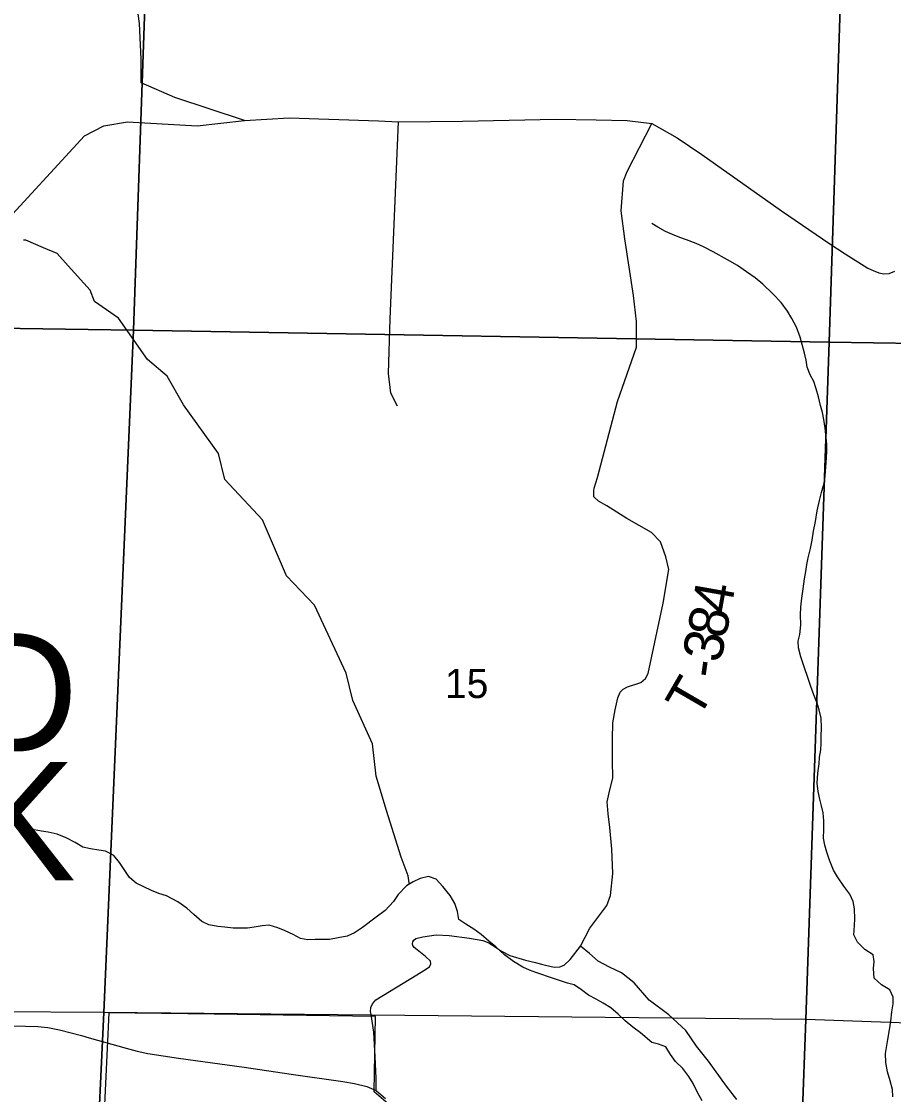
# Model space of a CAD drawing. Extents: x 0 to 34, y 0 to 22.
# Drawn here: x 3.296 to 4.552, y 15.005 to 16.55 of the extents above; entities that cross this region are included whole.
import ezdxf

# ---------------------------------------------------------------- set-up
doc = ezdxf.new("R2010")
doc.units = 0
for name, color, linetype in [('Default', 7, 'Continuous'), ('GM_X_County_Road', 7, 'Continuous'), ('GM_X_Minor_River', 7, 'Continuous'), ('GM_X_Section', 7, 'Continuous'), ('GM_X_Section_Text', 7, 'Continuous'), ('GM_X_Township_Road', 7, 'Continuous'), ('GM_X_Township_Road_Text', 7, 'Continuous'), ('GM_X_Township_Text', 7, 'Continuous')]:
    doc.layers.add(name, color=color, linetype=linetype)

msp = doc.modelspace()

# ---------------------------------------------------------------- linework, layer by layer
at = {"layer": 'Default'}
for p, q in [((3.4148, 15.1232), (2.428, 15.1288)), ((3.3681, 14.1), (3.4148, 15.1232)), ((3.4148, 15.1232), (3.3681, 14.1)), ((3.4223, 15.1228), (3.389, 14.4392)), ((4.4256, 15.1132), (3.4148, 15.1232)), ((3.5737, 15.1206), (3.4223, 15.1228)), ((3.8059, 15.1172), (3.5737, 15.1206)), ((3.8044, 15.0089), (3.8059, 15.1172)), ((4.3897, 14.1), (4.4256, 15.1132)), ((4.4256, 15.1132), (4.3897, 14.1)), ((5.4229, 15.0756), (4.4256, 15.1132)), ((3.8279, 14.9887), (3.8044, 15.0089))]:
    msp.add_line(p, q, dxfattribs=at)
at = {"layer": 'GM_X_County_Road'}
for p, q in [((3.4149, 16.3993), (3.4489, 16.405)), ((3.4489, 16.405), (3.457, 16.4045)), ((3.457, 16.4045), (3.5495, 16.3993)), ((3.5495, 16.3993), (3.6176, 16.4072)), ((3.6176, 16.4072), (3.682, 16.4109)), ((3.682, 16.4109), (3.8102, 16.4064)), ((3.8102, 16.4064), (3.8391, 16.4054)), ((3.8391, 16.4054), (3.9312, 16.4062)), ((3.9312, 16.4062), (4.0658, 16.4089)), ((4.0658, 16.4089), (4.1237, 16.4082)), ((4.1237, 16.4082), (4.1687, 16.4072)), ((4.1687, 16.4072), (4.204, 16.4026)), ((3.387, 16.3849), (3.4149, 16.3993)), ((4.204, 16.4026), (4.2406, 16.3821)), ((3.1953, 16.1767), (3.387, 16.3849)), ((4.2406, 16.3821), (4.276, 16.358)), ((4.276, 16.358), (4.3909, 16.2772)), ((4.3909, 16.2772), (4.4602, 16.2296)), ((4.4602, 16.2296), (4.4825, 16.215)), ((4.4825, 16.215), (4.5149, 16.1947)), ((4.5149, 16.1947), (4.5227, 16.1911)), ((4.5227, 16.1911), (4.5309, 16.1878)), ((4.5459, 16.1869), (4.5541, 16.19)), ((4.5309, 16.1878), (4.5379, 16.1864)), ((4.5379, 16.1864), (4.5459, 16.1869)), ((3.2648, 15.104), (3.302, 15.1035)), ((3.302, 15.1035), (3.3198, 15.1028)), ((3.3198, 15.1028), (3.3345, 15.1014)), ((3.3345, 15.1014), (3.3509, 15.0983)), ((3.3509, 15.0983), (3.383, 15.0898)), ((3.383, 15.0898), (3.3936, 15.0868)), ((3.3936, 15.0868), (3.4469, 15.0716)), ((3.4469, 15.0716), (3.4631, 15.0672)), ((3.4631, 15.0672), (3.4785, 15.0639)), ((3.4785, 15.0639), (3.5226, 15.0573)), ((3.5226, 15.0573), (3.6172, 15.0446)), ((3.6172, 15.0446), (3.6849, 15.0343)), ((3.6849, 15.0343), (3.759, 15.0237)), ((3.759, 15.0237), (3.776, 15.0208)), ((3.776, 15.0208), (3.7937, 15.0168)), ((3.7937, 15.0168), (3.8069, 15.0107)), ((3.8069, 15.0107), (3.8205, 14.9991))]:
    msp.add_line(p, q, dxfattribs=at)
at = {"layer": 'GM_X_Minor_River'}
for p, q in [((4.2127, 16.2536), (4.2038, 16.259)), ((4.2236, 16.2471), (4.2127, 16.2536)), ((3.3027, 16.235), (3.2993, 16.2349)), ((3.3282, 16.224), (3.3027, 16.235)), ((4.2336, 16.2428), (4.2236, 16.2471)), ((4.2444, 16.2386), (4.2336, 16.2428)), ((4.254, 16.2355), (4.2444, 16.2386)), ((4.2678, 16.2302), (4.254, 16.2355)), ((3.348, 16.2155), (3.3282, 16.224)), ((4.2786, 16.2252), (4.2678, 16.2302)), ((4.2921, 16.218), (4.2786, 16.2252)), ((3.3638, 16.1979), (3.348, 16.2155)), ((4.313, 16.2065), (4.2921, 16.218)), ((4.3273, 16.1982), (4.313, 16.2065)), ((3.3954, 16.1631), (3.3638, 16.1979)), ((4.3405, 16.1894), (4.3273, 16.1982)), ((4.3526, 16.1807), (4.3405, 16.1894)), ((4.3639, 16.1715), (4.3526, 16.1807)), ((3.4014, 16.1464), (3.3954, 16.1631)), ((4.378, 16.1575), (4.3639, 16.1715)), ((4.3902, 16.1449), (4.378, 16.1575)), ((3.4362, 16.1227), (3.4014, 16.1464)), ((4.3993, 16.1327), (4.3902, 16.1449)), ((4.4057, 16.1222), (4.3993, 16.1327)), ((3.4777, 16.0629), (3.4362, 16.1227)), ((4.4122, 16.1095), (4.4057, 16.1222)), ((4.4176, 16.0952), (4.4122, 16.1095)), ((4.4206, 16.0846), (4.4176, 16.0952)), ((4.4236, 16.0721), (4.4206, 16.0846)), ((4.4262, 16.0623), (4.4236, 16.0721)), ((3.5061, 16.039), (3.4777, 16.0629)), ((4.4277, 16.0521), (4.4262, 16.0623)), ((4.4318, 16.0412), (4.4277, 16.0521)), ((3.5299, 15.9976), (3.5061, 16.039)), ((4.4371, 16.0315), (4.4318, 16.0412)), ((4.4408, 16.0206), (4.4371, 16.0315)), ((4.4442, 16.0092), (4.4408, 16.0206)), ((4.4469, 15.9968), (4.4442, 16.0092)), ((3.5799, 15.9277), (3.5299, 15.9976)), ((4.4495, 15.9866), (4.4469, 15.9968)), ((4.4517, 15.9767), (4.4495, 15.9866)), ((4.4536, 15.9643), (4.4517, 15.9767)), ((4.4562, 15.9411), (4.4536, 15.9643)), ((4.4561, 15.9316), (4.4562, 15.9411)), ((3.5892, 15.8905), (3.5799, 15.9277)), ((4.4553, 15.9213), (4.4561, 15.9316)), ((4.4546, 15.9087), (4.4553, 15.9213)), ((4.4522, 15.8851), (4.4535, 15.895)), ((4.4535, 15.895), (4.4546, 15.9087)), ((3.6435, 15.8325), (3.5892, 15.8905)), ((4.4485, 15.8716), (4.4522, 15.8851)), ((4.4454, 15.8601), (4.4485, 15.8716)), ((4.4421, 15.8452), (4.4454, 15.8601)), ((4.4395, 15.8299), (4.4421, 15.8452)), ((3.6778, 15.7517), (3.6435, 15.8325)), ((4.4369, 15.8161), (4.4395, 15.8299)), ((4.4324, 15.7912), (4.4347, 15.8031)), ((4.4347, 15.8031), (4.4369, 15.8161)), ((4.429, 15.7774), (4.4324, 15.7912)), ((4.4274, 15.7679), (4.429, 15.7774)), ((4.4238, 15.7472), (4.4258, 15.7579)), ((4.4258, 15.7579), (4.4274, 15.7679)), ((3.7183, 15.7094), (3.6778, 15.7517)), ((4.422, 15.7331), (4.4238, 15.7472)), ((4.4202, 15.7193), (4.422, 15.7331)), ((3.7638, 15.6116), (3.7183, 15.7094)), ((4.4183, 15.7067), (4.4202, 15.7193)), ((4.4182, 15.6953), (4.4183, 15.7067)), ((4.4187, 15.6812), (4.4182, 15.6953)), ((4.4172, 15.6671), (4.4187, 15.6812)), ((4.4149, 15.6575), (4.4172, 15.6671)), ((4.4151, 15.648), (4.4149, 15.6575)), ((4.4186, 15.6352), (4.4151, 15.648)), ((4.424, 15.6194), (4.4186, 15.6352)), ((4.4286, 15.6055), (4.424, 15.6194)), ((3.7736, 15.5723), (3.7638, 15.6116)), ((4.4329, 15.5923), (4.4286, 15.6055)), ((4.4374, 15.5803), (4.4329, 15.5923)), ((3.8019, 15.5096), (3.7736, 15.5723)), ((4.442, 15.5686), (4.4374, 15.5803)), ((4.4449, 15.5588), (4.442, 15.5686)), ((4.4476, 15.5467), (4.4449, 15.5588)), ((4.4484, 15.5334), (4.4476, 15.5467)), ((4.448, 15.5205), (4.4484, 15.5334)), ((3.8069, 15.4633), (3.8019, 15.5096)), ((4.4471, 15.5011), (4.4476, 15.5106)), ((4.4476, 15.5106), (4.448, 15.5205)), ((4.4455, 15.4907), (4.4471, 15.5011)), ((4.4428, 15.4678), (4.4447, 15.4808)), ((4.4447, 15.4808), (4.4455, 15.4907)), ((3.8218, 15.4141), (3.8069, 15.4633)), ((4.4421, 15.453), (4.4428, 15.4678)), ((4.4437, 15.4412), (4.4421, 15.453)), ((4.4459, 15.4303), (4.4437, 15.4412)), ((4.4485, 15.4205), (4.4459, 15.4303)), ((4.4507, 15.4103), (4.4485, 15.4205)), ((3.843, 15.3468), (3.8218, 15.4141)), ((4.4518, 15.3989), (4.4507, 15.4103)), ((3.304, 15.3876), (3.2934, 15.3872)), ((3.3147, 15.386), (3.304, 15.3876)), ((3.3254, 15.384), (3.3147, 15.386)), ((4.4514, 15.3742), (4.4518, 15.3867)), ((4.4518, 15.3867), (4.4518, 15.3989)), ((3.335, 15.3828), (3.3254, 15.384)), ((3.3476, 15.3798), (3.335, 15.3828)), ((3.3607, 15.3745), (3.3476, 15.3798)), ((3.3735, 15.368), (3.3607, 15.3745)), ((4.4529, 15.3639), (4.4514, 15.3742)), ((3.3847, 15.3612), (3.3735, 15.368)), ((3.3958, 15.3585), (3.3847, 15.3612)), ((3.4076, 15.3569), (3.3958, 15.3585)), ((3.4172, 15.3553), (3.4076, 15.3569)), ((3.4292, 15.3493), (3.4172, 15.3553)), ((4.4559, 15.3537), (4.4529, 15.3639)), ((3.4375, 15.3389), (3.4292, 15.3493)), ((3.4443, 15.3288), (3.4375, 15.3389)), ((3.8533, 15.32), (3.843, 15.3468)), ((4.46, 15.3425), (4.4559, 15.3537)), ((4.4658, 15.3282), (4.46, 15.3425)), ((3.4518, 15.3173), (3.4443, 15.3288)), ((4.4711, 15.3185), (4.4658, 15.3282)), ((3.4616, 15.3092), (3.4518, 15.3173)), ((3.4724, 15.3042), (3.4616, 15.3092)), ((3.8604, 15.3113), (3.8507, 15.3053)), ((3.8546, 15.3097), (3.8533, 15.32)), ((3.8545, 15.3077), (3.8546, 15.3097)), ((3.8705, 15.3158), (3.8604, 15.3113)), ((3.8825, 15.3189), (3.8705, 15.3158)), ((3.8937, 15.315), (3.8825, 15.3189)), ((3.9032, 15.3043), (3.8937, 15.315)), ((4.4806, 15.3051), (4.4711, 15.3185)), ((3.4836, 15.2988), (3.4724, 15.3042)), ((3.494, 15.2942), (3.4836, 15.2988)), ((3.5051, 15.2908), (3.494, 15.2942)), ((3.8389, 15.2928), (3.832, 15.2827)), ((3.8507, 15.3053), (3.8389, 15.2928)), ((3.9134, 15.2913), (3.9032, 15.3043)), ((4.489, 15.2932), (4.4806, 15.3051)), ((4.4938, 15.2827), (4.489, 15.2932)), ((3.5214, 15.2822), (3.5051, 15.2908)), ((3.5346, 15.2731), (3.5214, 15.2822)), ((3.832, 15.2827), (3.8198, 15.2701)), ((3.9203, 15.2801), (3.9134, 15.2913)), ((3.9244, 15.2684), (3.9203, 15.2801)), ((4.4957, 15.2721), (4.4938, 15.2827)), ((3.5447, 15.2642), (3.5346, 15.2731)), ((3.5561, 15.2543), (3.5447, 15.2642)), ((3.8198, 15.2701), (3.8072, 15.2602)), ((3.9263, 15.2571), (3.9244, 15.2684)), ((4.4965, 15.258), (4.4957, 15.2721)), ((3.5661, 15.2493), (3.5561, 15.2543)), ((3.5791, 15.2467), (3.5661, 15.2493)), ((3.5894, 15.2459), (3.5791, 15.2467)), ((3.6012, 15.2447), (3.5894, 15.2459)), ((3.643, 15.2479), (3.6316, 15.2457)), ((3.6532, 15.2486), (3.643, 15.2479)), ((3.6655, 15.2452), (3.6532, 15.2486)), ((3.8072, 15.2602), (3.7875, 15.2456)), ((3.9364, 15.2502), (3.9263, 15.2571)), ((3.9476, 15.2429), (3.9364, 15.2502)), ((4.495, 15.2348), (4.4957, 15.2481)), ((4.4957, 15.2481), (4.4965, 15.258)), ((3.6119, 15.2443), (3.6012, 15.2447)), ((3.6218, 15.2446), (3.6119, 15.2443)), ((3.6316, 15.2457), (3.6218, 15.2446)), ((3.6759, 15.2406), (3.6655, 15.2452)), ((3.6875, 15.2352), (3.6759, 15.2406)), ((3.6983, 15.2295), (3.6875, 15.2352)), ((3.7655, 15.2331), (3.7523, 15.2304)), ((3.776, 15.2376), (3.7655, 15.2331)), ((3.7875, 15.2456), (3.776, 15.2376)), ((3.9581, 15.2356), (3.9476, 15.2429)), ((3.9691, 15.2257), (3.9581, 15.2356)), ((4.5002, 15.2243), (4.495, 15.2348)), ((3.7086, 15.2279), (3.6983, 15.2295)), ((3.7192, 15.2282), (3.7086, 15.2279)), ((3.7398, 15.2281), (3.7192, 15.2282)), ((3.7523, 15.2304), (3.7398, 15.2281)), ((3.9792, 15.2177), (3.9691, 15.2257)), ((3.9918, 15.2063), (3.9792, 15.2177)), ((4.5105, 15.2136), (4.5002, 15.2243)), ((4.0046, 15.1964), (3.9918, 15.2063)), ((4.5228, 15.2063), (4.5105, 15.2136)), ((4.5239, 15.1965), (4.5228, 15.2063)), ((4.0182, 15.1884), (4.0046, 15.1964)), ((4.0278, 15.1842), (4.0182, 15.1884)), ((4.0382, 15.1803), (4.0278, 15.1842)), ((4.5231, 15.1862), (4.5239, 15.1965)), ((4.5243, 15.1725), (4.5231, 15.1862)), ((4.0609, 15.1726), (4.0382, 15.1803)), ((4.0724, 15.1688), (4.0609, 15.1726)), ((4.0828, 15.1653), (4.0724, 15.1688)), ((4.5348, 15.163), (4.5243, 15.1725)), ((4.0923, 15.163), (4.0828, 15.1653)), ((4.1028, 15.1557), (4.0923, 15.163)), ((4.1126, 15.148), (4.1028, 15.1557)), ((4.5469, 15.1558), (4.5348, 15.163)), ((4.5517, 15.1453), (4.5469, 15.1558)), ((4.1238, 15.1423), (4.1126, 15.148)), ((4.1338, 15.1365), (4.1238, 15.1423)), ((4.5517, 15.1354), (4.5517, 15.1453)), ((4.1451, 15.13), (4.1338, 15.1365)), ((4.1556, 15.1208), (4.1451, 15.13)), ((4.5479, 15.1105), (4.5498, 15.1239)), ((4.5498, 15.1239), (4.5517, 15.1354)), ((4.1654, 15.1112), (4.1556, 15.1208)), ((4.1764, 15.1021), (4.1654, 15.1112)), ((4.546, 15.0983), (4.5479, 15.1105)), ((4.1876, 15.094), (4.1764, 15.1021)), ((4.204, 15.0797), (4.1876, 15.094)), ((4.5438, 15.0842), (4.546, 15.0983)), ((4.2136, 15.0773), (4.204, 15.0797)), ((4.224, 15.0735), (4.2136, 15.0773)), ((4.5406, 15.0639), (4.5438, 15.0842)), ((4.2308, 15.0627), (4.224, 15.0735)), ((4.2383, 15.0526), (4.2308, 15.0627)), ((4.541, 15.051), (4.5406, 15.0639)), ((4.2486, 15.0423), (4.2383, 15.0526)), ((4.5433, 15.0377), (4.541, 15.051)), ((4.2573, 15.0312), (4.2486, 15.0423)), ((4.2633, 15.0211), (4.2573, 15.0312)), ((4.5472, 15.0246), (4.5433, 15.0377)), ((4.2698, 15.008), (4.2633, 15.0211)), ((4.5506, 15.0121), (4.5472, 15.0246)), ((4.2766, 14.996), (4.2698, 15.008)), ((4.5509, 15.0019), (4.5506, 15.0121))]:
    msp.add_line(p, q, dxfattribs=at)
at = {"layer": 'GM_X_Section'}
for p, q in [((3.4934, 17.1171), (3.4577, 16.1051)), ((3.4577, 16.1051), (3.4934, 17.1171)), ((4.4928, 17.1099), (4.4591, 16.088)), ((4.4591, 16.088), (4.4928, 17.1099)), ((3.4577, 16.1051), (2.4631, 16.1204)), ((2.4631, 16.1204), (3.4577, 16.1051)), ((3.4577, 16.1051), (3.4148, 15.1232)), ((3.4148, 15.1232), (3.4577, 16.1051)), ((4.4591, 16.088), (3.4577, 16.1051)), ((3.4577, 16.1051), (4.4591, 16.088)), ((4.4591, 16.088), (4.4256, 15.1132)), ((4.4256, 15.1132), (4.4591, 16.088)), ((5.4597, 16.0717), (4.4591, 16.088)), ((4.4591, 16.088), (5.4597, 16.0717)), ((3.4148, 15.1232), (2.428, 15.1288)), ((4.4256, 15.1132), (3.4148, 15.1232)), ((5.4229, 15.0756), (4.4256, 15.1132))]:
    msp.add_line(p, q, dxfattribs=at)
at = {"layer": 'GM_X_Township_Road'}
for p, q in [((3.4665, 16.5468), (3.4643, 16.5605)), ((3.4685, 16.4953), (3.4665, 16.5468)), ((3.4685, 16.4612), (3.4685, 16.4953)), ((3.517, 16.4401), (3.4685, 16.4612)), ((3.6176, 16.4072), (3.517, 16.4401)), ((3.8274, 16.1216), (3.8391, 16.4054)), ((4.1683, 16.3338), (4.204, 16.4026)), ((4.1634, 16.3203), (4.1683, 16.3338)), ((4.1597, 16.2772), (4.1634, 16.3203)), ((4.1649, 16.2367), (4.1597, 16.2772)), ((4.1776, 16.1551), (4.1649, 16.2367)), ((4.1818, 16.118), (4.1776, 16.1551)), ((3.8248, 16.0431), (3.8274, 16.1216)), ((4.1818, 16.0809), (4.1818, 16.118)), ((4.1548, 16.0027), (4.1818, 16.0809)), ((3.8281, 16.0146), (3.8248, 16.0431)), ((3.8378, 15.9958), (3.8281, 16.0146)), ((4.126, 15.8931), (4.1548, 16.0027)), ((4.1208, 15.878), (4.126, 15.8931)), ((4.1205, 15.8655), (4.1207, 15.8742)), ((4.1274, 15.8589), (4.1205, 15.8655)), ((4.1207, 15.8742), (4.1208, 15.878)), ((4.1394, 15.8524), (4.1274, 15.8589)), ((4.1678, 15.8343), (4.1394, 15.8524)), ((4.2036, 15.8141), (4.1678, 15.8343)), ((4.2167, 15.8005), (4.2036, 15.8141)), ((4.224, 15.7792), (4.2167, 15.8005)), ((4.2284, 15.7606), (4.224, 15.7792)), ((4.2201, 15.7121), (4.2284, 15.7606)), ((4.2084, 15.6563), (4.2201, 15.7121)), ((4.1989, 15.6109), (4.2084, 15.6563)), ((4.188, 15.5982), (4.195, 15.6041)), ((4.195, 15.6041), (4.1989, 15.6109)), ((4.1582, 15.5842), (4.1626, 15.5883)), ((4.1626, 15.5883), (4.169, 15.5921)), ((4.169, 15.5921), (4.188, 15.5982)), ((4.1511, 15.559), (4.1552, 15.576)), ((4.1552, 15.576), (4.1582, 15.5842)), ((4.148, 15.54), (4.1511, 15.559)), ((4.1472, 15.5165), (4.148, 15.54)), ((4.1473, 15.4852), (4.1472, 15.5165)), ((4.1477, 15.4607), (4.1473, 15.4852)), ((4.1428, 15.4394), (4.1477, 15.4607)), ((4.1398, 15.4262), (4.1428, 15.4394)), ((4.1411, 15.4093), (4.1398, 15.4262)), ((4.1433, 15.3896), (4.1411, 15.4093)), ((4.1465, 15.3582), (4.1433, 15.3896)), ((4.1477, 15.3234), (4.1465, 15.3582)), ((4.1447, 15.2915), (4.1477, 15.3234)), ((4.1146, 15.2447), (4.1392, 15.2772)), ((4.1392, 15.2772), (4.1447, 15.2915)), ((3.8641, 15.2298), (3.8745, 15.2321)), ((3.8745, 15.2321), (3.8937, 15.2348)), ((3.8937, 15.2348), (3.9123, 15.2339)), ((3.9123, 15.2339), (3.9413, 15.2302)), ((4.1013, 15.2188), (4.1146, 15.2447)), ((3.8594, 15.2219), (3.8599, 15.2246)), ((3.86, 15.2196), (3.8594, 15.2219)), ((3.8599, 15.2246), (3.8613, 15.2273)), ((3.8619, 15.2168), (3.86, 15.2196)), ((3.8613, 15.2273), (3.8641, 15.2298)), ((3.8663, 15.2133), (3.8619, 15.2168)), ((3.9413, 15.2302), (3.9607, 15.2265)), ((3.9607, 15.2265), (3.9693, 15.2234)), ((3.9693, 15.2234), (3.9746, 15.2202)), ((3.9746, 15.2202), (3.9873, 15.2115)), ((4.0866, 15.1994), (4.1013, 15.2188)), ((4.1143, 15.2082), (4.1013, 15.2188)), ((3.8779, 15.2037), (3.8663, 15.2133)), ((3.8855, 15.197), (3.8779, 15.2037)), ((3.9873, 15.2115), (3.9993, 15.2049)), ((3.9993, 15.2049), (4.0222, 15.1985)), ((4.1267, 15.1972), (4.1143, 15.2082)), ((3.8759, 15.1835), (3.8838, 15.1888)), ((3.8838, 15.1888), (3.886, 15.193)), ((3.886, 15.193), (3.8855, 15.197)), ((4.0222, 15.1985), (4.0367, 15.1952)), ((4.0367, 15.1952), (4.0452, 15.1927)), ((4.0452, 15.1927), (4.0509, 15.191)), ((4.0509, 15.191), (4.0635, 15.1882)), ((4.0635, 15.1882), (4.0715, 15.1889)), ((4.0715, 15.1889), (4.0779, 15.1912)), ((4.0779, 15.1912), (4.0866, 15.1994)), ((4.1429, 15.1884), (4.1267, 15.1972)), ((4.1602, 15.1802), (4.1429, 15.1884)), ((3.8064, 15.1413), (3.8658, 15.1775)), ((3.8658, 15.1775), (3.8759, 15.1835)), ((4.1784, 15.1659), (4.1602, 15.1802)), ((4.2002, 15.1409), (4.1784, 15.1659)), ((3.8018, 15.1357), (3.8064, 15.1413)), ((4.2283, 15.1195), (4.2002, 15.1409)), ((3.7991, 15.1244), (3.7992, 15.1302)), ((3.7997, 15.1204), (3.7991, 15.1244)), ((3.7992, 15.1302), (3.8018, 15.1357)), ((3.8035, 15.0947), (3.7997, 15.1204)), ((4.2529, 15.0972), (4.2283, 15.1195)), ((3.8054, 15.0591), (3.8035, 15.0947)), ((4.2684, 15.0746), (4.2529, 15.0972)), ((4.2856, 15.053), (4.2684, 15.0746)), ((3.807, 15.0286), (3.8054, 15.0591)), ((4.3116, 15.0169), (4.2856, 15.053)), ((3.8069, 15.0107), (3.807, 15.0286)), ((4.3262, 14.9977), (4.3116, 15.0169))]:
    msp.add_line(p, q, dxfattribs=at)

# ---------------------------------------------------------------- texts
at = {"layer": 'GM_X_Section_Text'}
msp.add_text('15', height=0.04186, rotation=0, dxfattribs=at).set_placement((3.9063, 15.5758))
at = {"layer": 'GM_X_Township_Road_Text'}
for s, rotation, p in [('4', 79.9925, (4.317, 15.6953)), ('8', 78.7514, (4.31, 15.6597)), ('3', 78.3461, (4.3028, 15.625)), ('-', 81.9377, (4.2997, 15.6028)), ('T', 59.8697, (4.2706, 15.5436))]:
    msp.add_text(s, height=0.0568, rotation=rotation, dxfattribs=at).set_placement(p)
at = {"layer": 'GM_X_Township_Text'}
for s, p in [('ISLAND', (2.5546, 15.4988)), ('CREEK', (2.5892, 15.3133))]:
    msp.add_text(s, height=0.17045, rotation=0, dxfattribs=at).set_placement(p)

doc.saveas('drawing.dxf')
